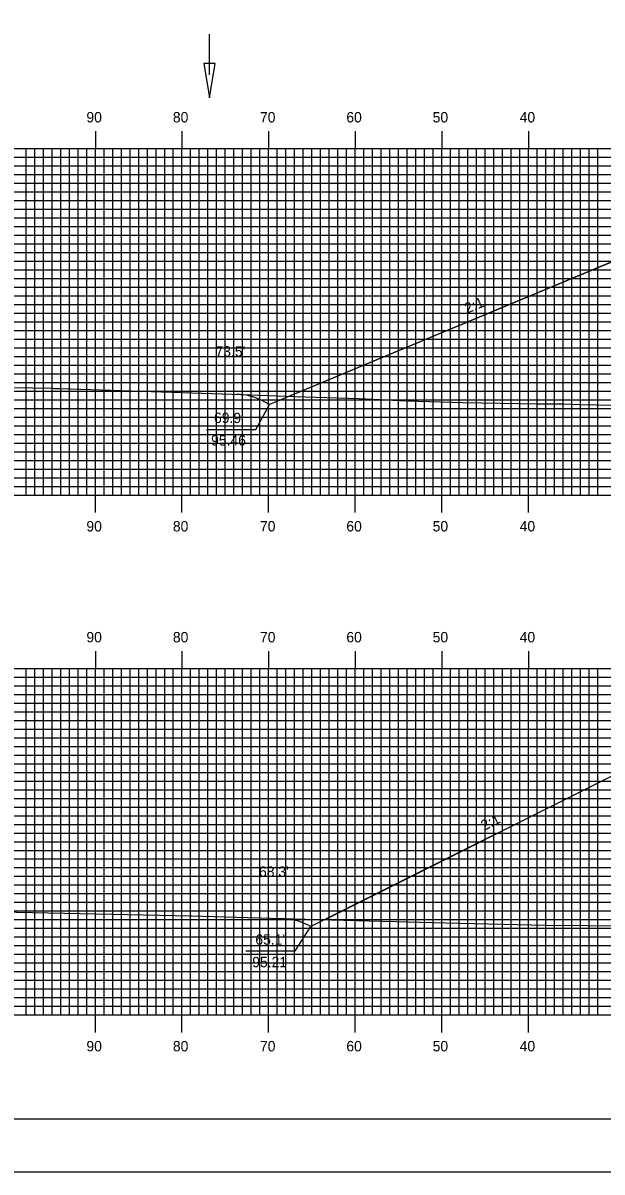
# Model space of a CAD drawing. Extents: x 1786582 to 1786926, y 442591 to 442811.
# Drawn here: x 1786649.7 to 1786716.6, y 442590.5 to 442723.1 of the extents above; entities that cross this region are included whole.
import ezdxf

# ---------------------------------------------------------------- set-up
doc = ezdxf.new("R2010")
doc.units = 0
for name, color, linetype in [('ANNOTATION', 7, 'Continuous'), ('BORDER', 7, 'Continuous'), ('D_Drainage_Ditch_Line', 7, 'Continuous'), ('D_Roadway_Centerline', 7, 'Continuous'), ('D_Roadway_FinishedGrade', 7, 'Continuous'), ('D_Roadway_SlopeLines', 7, 'Continuous'), ('D_Text_Standard', 7, 'Continuous'), ('H_V ANNOTATION', 7, 'Continuous'), ('MAJOR', 7, 'Continuous'), ('MINOR', 7, 'Continuous'), ('PLOT BOUNDARY', 7, 'Continuous'), ('S_Roadway_Centerline', 7, 'Continuous')]:
    doc.layers.add(name, color=color, linetype=linetype)

msp = doc.modelspace()

# ---------------------------------------------------------------- linework, layer by layer
at = {"layer": 'ANNOTATION'}
for points in [[(1786670.91, 442676.25), (1786676.6, 442676.25), (1786678.19, 442679.13)], [(1786675.44, 442616.06), (1786681.13, 442616.06), (1786682.95, 442618.88)]]:
    msp.add_lwpolyline(points, dxfattribs=at)
at = {"layer": 'BORDER'}
msp.add_lwpolyline([(1786598.48, 442596.67), (1786918.48, 442596.67), (1786918.48, 442806.67), (1786598.48, 442806.67)], close=True, dxfattribs=at)
at = {"layer": 'D_Drainage_Ditch_Line'}
msp.add_line((1786671.24, 442717.15), (1786671.24, 442721.85), dxfattribs=at)
msp.add_lwpolyline([(1786671.9, 442718.46), (1786670.59, 442718.46), (1786671.24, 442714.52)], close=True, dxfattribs=at)
at = {"layer": 'D_Roadway_Centerline'}
for points in [[(1786680.45, 442680.07), (1786719.25, 442696.23), (1786725.08, 442698.66), (1786728.08, 442698.78), (1786736.08, 442699.1), (1786748.08, 442699.36), (1786760.08, 442699.63), (1786768.08, 442699.31), (1786771.08, 442699.19), (1786775.83, 442696.81), (1786813.07, 442678.19)], [(1786684.52, 442619.66), (1786720.26, 442637.53), (1786725.08, 442639.94), (1786728.08, 442640.06), (1786736.08, 442640.38), (1786748.08, 442640.64), (1786760.08, 442640.9), (1786768.08, 442640.58), (1786771.08, 442640.46), (1786775.83, 442638.09), (1786815.96, 442618.02)]]:
    msp.add_lwpolyline(points, dxfattribs=at)
at = {"layer": 'D_Roadway_FinishedGrade'}
for p, q in [((1786678.19, 442679.13), (1786677.29, 442679.58)), ((1786682.95, 442618.88), (1786682.58, 442619.06))]:
    msp.add_line(p, q, dxfattribs=at)
for centre, end in [((1786674.16, 442673.32), 87.5804), ((1786679.45, 442612.8), 88.2054)]:
    msp.add_arc(centre, 7, 63.4349, end, dxfattribs=at)
at = {"layer": 'D_Roadway_SlopeLines'}
for points in [[(1786725.08, 442698.66), (1786678.19, 442679.13)], [(1786725.08, 442639.94), (1786682.95, 442618.88)]]:
    msp.add_lwpolyline(points, dxfattribs=at)
at = {"layer": 'MAJOR'}
for p, q in [((1786658.08, 442710.67), (1786658.08, 442708.67)), ((1786668.08, 442710.67), (1786668.08, 442708.67)), ((1786678.08, 442710.67), (1786678.08, 442708.67)), ((1786688.08, 442710.67), (1786688.08, 442708.67)), ((1786698.08, 442710.67), (1786698.08, 442708.67)), ((1786708.08, 442710.67), (1786708.08, 442708.67)), ((1786608.08, 442708.67), (1786888.08, 442708.67)), ((1786608.08, 442708.67), (1786888.08, 442708.67)), ((1786658.08, 442668.67), (1786658.08, 442708.67)), ((1786668.08, 442668.67), (1786668.08, 442708.67)), ((1786678.08, 442668.67), (1786678.08, 442708.67)), ((1786688.08, 442668.67), (1786688.08, 442708.67)), ((1786698.08, 442668.67), (1786698.08, 442708.67)), ((1786708.08, 442668.67), (1786708.08, 442708.67)), ((1786608.08, 442703.67), (1786888.08, 442703.67)), ((1786608.08, 442698.67), (1786888.08, 442698.67)), ((1786608.08, 442693.67), (1786888.08, 442693.67)), ((1786608.08, 442688.67), (1786888.08, 442688.67)), ((1786608.08, 442683.67), (1786888.08, 442683.67)), ((1786608.08, 442678.67), (1786888.08, 442678.67)), ((1786608.08, 442673.67), (1786888.08, 442673.67)), ((1786608.08, 442668.67), (1786888.08, 442668.67)), ((1786608.08, 442668.67), (1786888.08, 442668.67)), ((1786658.08, 442666.66), (1786658.08, 442668.67)), ((1786668.08, 442666.66), (1786668.08, 442668.67)), ((1786678.08, 442666.66), (1786678.08, 442668.67)), ((1786688.08, 442666.66), (1786688.08, 442668.67)), ((1786698.08, 442666.66), (1786698.08, 442668.67)), ((1786708.08, 442666.66), (1786708.08, 442668.67)), ((1786658.08, 442650.67), (1786658.08, 442648.67)), ((1786668.08, 442650.67), (1786668.08, 442648.67)), ((1786678.08, 442650.67), (1786678.08, 442648.67)), ((1786688.08, 442650.67), (1786688.08, 442648.67)), ((1786698.08, 442650.67), (1786698.08, 442648.67)), ((1786708.08, 442650.67), (1786708.08, 442648.67)), ((1786608.08, 442648.67), (1786888.08, 442648.67)), ((1786608.08, 442648.67), (1786888.08, 442648.67)), ((1786658.08, 442608.67), (1786658.08, 442648.67)), ((1786668.08, 442608.67), (1786668.08, 442648.67)), ((1786678.08, 442608.67), (1786678.08, 442648.67)), ((1786688.08, 442608.67), (1786688.08, 442648.67)), ((1786698.08, 442608.67), (1786698.08, 442648.67)), ((1786708.08, 442608.67), (1786708.08, 442648.67)), ((1786608.08, 442643.67), (1786888.08, 442643.67)), ((1786608.08, 442638.67), (1786888.08, 442638.67)), ((1786608.08, 442633.67), (1786888.08, 442633.67)), ((1786608.08, 442628.67), (1786888.08, 442628.67)), ((1786608.08, 442623.67), (1786888.08, 442623.67)), ((1786608.08, 442618.67), (1786888.08, 442618.67)), ((1786608.08, 442613.67), (1786888.08, 442613.67)), ((1786608.08, 442608.67), (1786888.08, 442608.67)), ((1786608.08, 442608.67), (1786888.08, 442608.67)), ((1786658.08, 442606.66), (1786658.08, 442608.67)), ((1786668.08, 442606.66), (1786668.08, 442608.67)), ((1786678.08, 442606.66), (1786678.08, 442608.67)), ((1786688.08, 442606.66), (1786688.08, 442608.67)), ((1786698.08, 442606.66), (1786698.08, 442608.67)), ((1786708.08, 442606.66), (1786708.08, 442608.67))]:
    msp.add_line(p, q, dxfattribs=at)
at = {"layer": 'MINOR'}
for p, q in [((1786650.08, 442668.67), (1786650.08, 442708.67)), ((1786651.08, 442668.67), (1786651.08, 442708.67)), ((1786652.08, 442668.67), (1786652.08, 442708.67)), ((1786653.08, 442668.67), (1786653.08, 442708.67)), ((1786654.08, 442668.67), (1786654.08, 442708.67)), ((1786655.08, 442668.67), (1786655.08, 442708.67)), ((1786656.08, 442668.67), (1786656.08, 442708.67)), ((1786657.08, 442668.67), (1786657.08, 442708.67)), ((1786659.08, 442668.67), (1786659.08, 442708.67)), ((1786660.08, 442668.67), (1786660.08, 442708.67)), ((1786661.08, 442668.67), (1786661.08, 442708.67)), ((1786662.08, 442668.67), (1786662.08, 442708.67)), ((1786663.08, 442668.67), (1786663.08, 442708.67)), ((1786664.08, 442668.67), (1786664.08, 442708.67)), ((1786665.08, 442668.67), (1786665.08, 442708.67)), ((1786666.08, 442668.67), (1786666.08, 442708.67)), ((1786667.08, 442668.67), (1786667.08, 442708.67)), ((1786669.08, 442668.67), (1786669.08, 442708.67)), ((1786670.08, 442668.67), (1786670.08, 442708.67)), ((1786671.08, 442668.67), (1786671.08, 442708.67)), ((1786672.08, 442668.67), (1786672.08, 442708.67)), ((1786673.08, 442668.67), (1786673.08, 442708.67)), ((1786674.08, 442668.67), (1786674.08, 442708.67)), ((1786675.08, 442668.67), (1786675.08, 442708.67)), ((1786676.08, 442668.67), (1786676.08, 442708.67)), ((1786677.08, 442668.67), (1786677.08, 442708.67)), ((1786679.08, 442668.67), (1786679.08, 442708.67)), ((1786680.08, 442668.67), (1786680.08, 442708.67)), ((1786681.08, 442668.67), (1786681.08, 442708.67)), ((1786682.08, 442668.67), (1786682.08, 442708.67)), ((1786683.08, 442668.67), (1786683.08, 442708.67)), ((1786684.08, 442668.67), (1786684.08, 442708.67)), ((1786685.08, 442668.67), (1786685.08, 442708.67)), ((1786686.08, 442668.67), (1786686.08, 442708.67)), ((1786687.08, 442668.67), (1786687.08, 442708.67)), ((1786689.08, 442668.67), (1786689.08, 442708.67)), ((1786690.08, 442668.67), (1786690.08, 442708.67)), ((1786691.08, 442668.67), (1786691.08, 442708.67)), ((1786692.08, 442668.67), (1786692.08, 442708.67)), ((1786693.08, 442668.67), (1786693.08, 442708.67)), ((1786694.08, 442668.67), (1786694.08, 442708.67)), ((1786695.08, 442668.67), (1786695.08, 442708.67)), ((1786696.08, 442668.67), (1786696.08, 442708.67)), ((1786697.08, 442668.67), (1786697.08, 442708.67)), ((1786699.08, 442668.67), (1786699.08, 442708.67)), ((1786700.08, 442668.67), (1786700.08, 442708.67)), ((1786701.08, 442668.67), (1786701.08, 442708.67)), ((1786702.08, 442668.67), (1786702.08, 442708.67)), ((1786703.08, 442668.67), (1786703.08, 442708.67)), ((1786704.08, 442668.67), (1786704.08, 442708.67)), ((1786705.08, 442668.67), (1786705.08, 442708.67)), ((1786706.08, 442668.67), (1786706.08, 442708.67)), ((1786707.08, 442668.67), (1786707.08, 442708.67)), ((1786709.08, 442668.67), (1786709.08, 442708.67)), ((1786710.08, 442668.67), (1786710.08, 442708.67)), ((1786711.08, 442668.67), (1786711.08, 442708.67)), ((1786712.08, 442668.67), (1786712.08, 442708.67)), ((1786713.08, 442668.67), (1786713.08, 442708.67)), ((1786714.08, 442668.67), (1786714.08, 442708.67)), ((1786715.08, 442668.67), (1786715.08, 442708.67)), ((1786716.08, 442668.67), (1786716.08, 442708.67)), ((1786608.08, 442707.67), (1786888.08, 442707.67)), ((1786608.08, 442706.67), (1786888.08, 442706.67)), ((1786608.08, 442705.67), (1786888.08, 442705.67)), ((1786608.08, 442704.67), (1786888.08, 442704.67)), ((1786608.08, 442702.67), (1786888.08, 442702.67)), ((1786608.08, 442701.67), (1786888.08, 442701.67)), ((1786608.08, 442700.67), (1786888.08, 442700.67)), ((1786608.08, 442699.67), (1786888.08, 442699.67)), ((1786608.08, 442697.67), (1786888.08, 442697.67)), ((1786608.08, 442696.67), (1786888.08, 442696.67)), ((1786608.08, 442695.67), (1786888.08, 442695.67)), ((1786608.08, 442694.67), (1786888.08, 442694.67)), ((1786608.08, 442692.67), (1786888.08, 442692.67)), ((1786608.08, 442691.67), (1786888.08, 442691.67)), ((1786608.08, 442690.67), (1786888.08, 442690.67)), ((1786608.08, 442689.67), (1786888.08, 442689.67)), ((1786608.08, 442687.67), (1786888.08, 442687.67)), ((1786608.08, 442686.67), (1786888.08, 442686.67)), ((1786608.08, 442685.67), (1786888.08, 442685.67)), ((1786608.08, 442684.67), (1786888.08, 442684.67)), ((1786608.08, 442682.67), (1786888.08, 442682.67)), ((1786608.08, 442681.67), (1786888.08, 442681.67)), ((1786608.08, 442680.67), (1786888.08, 442680.67)), ((1786608.08, 442679.67), (1786888.08, 442679.67)), ((1786608.08, 442677.67), (1786888.08, 442677.67)), ((1786608.08, 442676.67), (1786888.08, 442676.67)), ((1786608.08, 442675.67), (1786888.08, 442675.67)), ((1786608.08, 442674.67), (1786888.08, 442674.67)), ((1786608.08, 442672.67), (1786888.08, 442672.67)), ((1786608.08, 442671.67), (1786888.08, 442671.67)), ((1786608.08, 442670.67), (1786888.08, 442670.67)), ((1786608.08, 442669.67), (1786888.08, 442669.67)), ((1786650.08, 442608.67), (1786650.08, 442648.67)), ((1786651.08, 442608.67), (1786651.08, 442648.67)), ((1786652.08, 442608.67), (1786652.08, 442648.67)), ((1786653.08, 442608.67), (1786653.08, 442648.67)), ((1786654.08, 442608.67), (1786654.08, 442648.67)), ((1786655.08, 442608.67), (1786655.08, 442648.67)), ((1786656.08, 442608.67), (1786656.08, 442648.67)), ((1786657.08, 442608.67), (1786657.08, 442648.67)), ((1786659.08, 442608.67), (1786659.08, 442648.67)), ((1786660.08, 442608.67), (1786660.08, 442648.67)), ((1786661.08, 442608.67), (1786661.08, 442648.67)), ((1786662.08, 442608.67), (1786662.08, 442648.67)), ((1786663.08, 442608.67), (1786663.08, 442648.67)), ((1786664.08, 442608.67), (1786664.08, 442648.67)), ((1786665.08, 442608.67), (1786665.08, 442648.67)), ((1786666.08, 442608.67), (1786666.08, 442648.67)), ((1786667.08, 442608.67), (1786667.08, 442648.67)), ((1786669.08, 442608.67), (1786669.08, 442648.67)), ((1786670.08, 442608.67), (1786670.08, 442648.67)), ((1786671.08, 442608.67), (1786671.08, 442648.67)), ((1786672.08, 442608.67), (1786672.08, 442648.67)), ((1786673.08, 442608.67), (1786673.08, 442648.67)), ((1786674.08, 442608.67), (1786674.08, 442648.67)), ((1786675.08, 442608.67), (1786675.08, 442648.67)), ((1786676.08, 442608.67), (1786676.08, 442648.67)), ((1786677.08, 442608.67), (1786677.08, 442648.67)), ((1786679.08, 442608.67), (1786679.08, 442648.67)), ((1786680.08, 442608.67), (1786680.08, 442648.67)), ((1786681.08, 442608.67), (1786681.08, 442648.67)), ((1786682.08, 442608.67), (1786682.08, 442648.67)), ((1786683.08, 442608.67), (1786683.08, 442648.67)), ((1786684.08, 442608.67), (1786684.08, 442648.67)), ((1786685.08, 442608.67), (1786685.08, 442648.67)), ((1786686.08, 442608.67), (1786686.08, 442648.67)), ((1786687.08, 442608.67), (1786687.08, 442648.67)), ((1786689.08, 442608.67), (1786689.08, 442648.67)), ((1786690.08, 442608.67), (1786690.08, 442648.67)), ((1786691.08, 442608.67), (1786691.08, 442648.67)), ((1786692.08, 442608.67), (1786692.08, 442648.67)), ((1786693.08, 442608.67), (1786693.08, 442648.67)), ((1786694.08, 442608.67), (1786694.08, 442648.67)), ((1786695.08, 442608.67), (1786695.08, 442648.67)), ((1786696.08, 442608.67), (1786696.08, 442648.67)), ((1786697.08, 442608.67), (1786697.08, 442648.67)), ((1786699.08, 442608.67), (1786699.08, 442648.67)), ((1786700.08, 442608.67), (1786700.08, 442648.67)), ((1786701.08, 442608.67), (1786701.08, 442648.67)), ((1786702.08, 442608.67), (1786702.08, 442648.67)), ((1786703.08, 442608.67), (1786703.08, 442648.67)), ((1786704.08, 442608.67), (1786704.08, 442648.67)), ((1786705.08, 442608.67), (1786705.08, 442648.67)), ((1786706.08, 442608.67), (1786706.08, 442648.67)), ((1786707.08, 442608.67), (1786707.08, 442648.67)), ((1786709.08, 442608.67), (1786709.08, 442648.67)), ((1786710.08, 442608.67), (1786710.08, 442648.67)), ((1786711.08, 442608.67), (1786711.08, 442648.67)), ((1786712.08, 442608.67), (1786712.08, 442648.67)), ((1786713.08, 442608.67), (1786713.08, 442648.67)), ((1786714.08, 442608.67), (1786714.08, 442648.67)), ((1786715.08, 442608.67), (1786715.08, 442648.67)), ((1786716.08, 442608.67), (1786716.08, 442648.67)), ((1786608.08, 442647.67), (1786888.08, 442647.67)), ((1786608.08, 442646.67), (1786888.08, 442646.67)), ((1786608.08, 442645.67), (1786888.08, 442645.67)), ((1786608.08, 442644.67), (1786888.08, 442644.67)), ((1786608.08, 442642.67), (1786888.08, 442642.67)), ((1786608.08, 442641.67), (1786888.08, 442641.67)), ((1786608.08, 442640.67), (1786888.08, 442640.67)), ((1786608.08, 442639.67), (1786888.08, 442639.67)), ((1786608.08, 442637.67), (1786888.08, 442637.67)), ((1786608.08, 442636.67), (1786888.08, 442636.67)), ((1786608.08, 442635.67), (1786888.08, 442635.67)), ((1786608.08, 442634.67), (1786888.08, 442634.67)), ((1786608.08, 442632.67), (1786888.08, 442632.67)), ((1786608.08, 442631.67), (1786888.08, 442631.67)), ((1786608.08, 442630.67), (1786888.08, 442630.67)), ((1786608.08, 442629.67), (1786888.08, 442629.67)), ((1786608.08, 442627.67), (1786888.08, 442627.67)), ((1786608.08, 442626.67), (1786888.08, 442626.67)), ((1786608.08, 442625.67), (1786888.08, 442625.67)), ((1786608.08, 442624.67), (1786888.08, 442624.67)), ((1786608.08, 442622.67), (1786888.08, 442622.67)), ((1786608.08, 442621.67), (1786888.08, 442621.67)), ((1786608.08, 442620.67), (1786888.08, 442620.67)), ((1786608.08, 442619.67), (1786888.08, 442619.67)), ((1786608.08, 442617.67), (1786888.08, 442617.67)), ((1786608.08, 442616.67), (1786888.08, 442616.67)), ((1786608.08, 442615.67), (1786888.08, 442615.67)), ((1786608.08, 442614.67), (1786888.08, 442614.67)), ((1786608.08, 442612.67), (1786888.08, 442612.67)), ((1786608.08, 442611.67), (1786888.08, 442611.67)), ((1786608.08, 442610.67), (1786888.08, 442610.67)), ((1786608.08, 442609.67), (1786888.08, 442609.67))]:
    msp.add_line(p, q, dxfattribs=at)
at = {"layer": 'PLOT BOUNDARY'}
msp.add_lwpolyline([(1786582.29, 442590.55), (1786922.29, 442590.55), (1786922.29, 442810.55), (1786582.29, 442810.55)], close=True, dxfattribs=at)
at = {"layer": 'S_Roadway_Centerline'}
for points in [[(1786608.08, 442682.03), (1786612.75, 442681.96), (1786618.09, 442681.75), (1786625.46, 442681.55), (1786633.23, 442681.35), (1786653.02, 442680.99), (1786653.17, 442680.99), (1786653.29, 442680.98), (1786654.05, 442680.96), (1786673.88, 442680.33), (1786676.91, 442680.21), (1786681.1, 442680.04), (1786688.53, 442679.81), (1786694.01, 442679.56), (1786700.51, 442679.34), (1786709.11, 442679.21), (1786711.98, 442679.2), (1786714.12, 442679.12), (1786728.66, 442678.82)], [(1786608.08, 442621.22), (1786608.31, 442621.22), (1786610.74, 442621.15), (1786614.04, 442621.13), (1786628.44, 442620.87), (1786641.57, 442620.64), (1786648.97, 442620.55), (1786669.14, 442620.13), (1786669.16, 442620.13), (1786669.17, 442620.13), (1786680.9, 442619.76), (1786689.69, 442619.52), (1786692.81, 442619.46), (1786696.92, 442619.35), (1786710.05, 442619.04), (1786724.45, 442618.91)]]:
    msp.add_lwpolyline(points, dxfattribs=at)

# ---------------------------------------------------------------- texts
at = {"layer": 'ANNOTATION'}
for rotation, p in [(22.6199, (1786701, 442689.6)), (26.5651, (1786702.95, 442629.91))]:
    msp.add_text('2:1', height=1.2, rotation=rotation, dxfattribs=at).set_placement(p)
for s, p in [("69.9' ", (1786671.78, 442676.98)), ('95.46', (1786671.44, 442674.38)), ("65.1' ", (1786676.55, 442616.78)), ('95.21', (1786676.19, 442614.18))]:
    msp.add_text(s, height=1.2, dxfattribs=at).set_placement(p)
at = {"layer": 'D_Text_Standard'}
for s, p in [("73.5'", (1786671.95, 442684.65)), ("68.3'", (1786676.97, 442624.61))]:
    msp.add_text(s, height=1.2, dxfattribs=at).set_placement(p)
at = {"layer": 'H_V ANNOTATION'}
for s, p in [('90', (1786657.05, 442711.67)), ('80', (1786667.03, 442711.67)), ('70', (1786677.08, 442711.67)), ('60', (1786687.05, 442711.67)), ('50', (1786697.01, 442711.67)), ('40', (1786707.05, 442711.67)), ('90', (1786657.05, 442664.47)), ('80', (1786667.03, 442664.47)), ('70', (1786677.08, 442664.47)), ('60', (1786687.05, 442664.47)), ('50', (1786697.01, 442664.47)), ('40', (1786707.05, 442664.47)), ('90', (1786657.05, 442651.67)), ('80', (1786667.03, 442651.67)), ('70', (1786677.08, 442651.67)), ('60', (1786687.05, 442651.67)), ('50', (1786697.01, 442651.67)), ('40', (1786707.05, 442651.67)), ('90', (1786657.05, 442604.47)), ('80', (1786667.03, 442604.47)), ('70', (1786677.08, 442604.47)), ('60', (1786687.05, 442604.47)), ('50', (1786697.01, 442604.47)), ('40', (1786707.05, 442604.47))]:
    msp.add_text(s, height=1.2, dxfattribs=at).set_placement(p)

doc.saveas('drawing.dxf')
